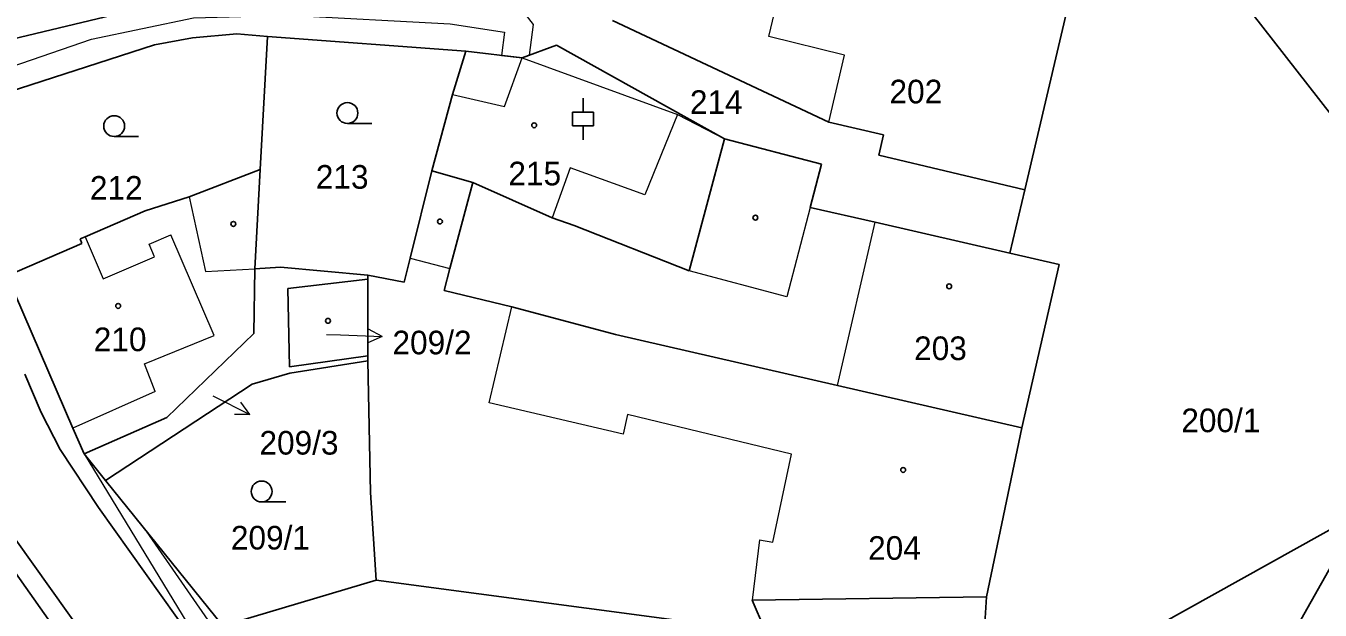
# Model space of a CAD drawing. Extents: x -727701 to -724405, y -960481 to -957284.
# Drawn here: x -726900.7 to -726807.6, y -958127.7 to -958085.7 of the extents above; entities that cross this region are included whole.
import ezdxf
from ezdxf.enums import TextEntityAlignment as Align

# ---------------------------------------------------------------- set-up
doc = ezdxf.new("R2010")
doc.units = 0
doc.header["$LTSCALE"] = 0.68
for name, color, linetype, lineweight in [('1', 7, 'Continuous', 25), ('13', 7, 'Continuous', 13), ('3', 7, 'Continuous', 25), ('4', 7, 'Continuous', 13), ('5', 7, 'Continuous', 25), ('7', 7, 'Continuous', 13)]:
    doc.layers.add(name, color=color, linetype=linetype, lineweight=lineweight)
doc.layers.add('2', color=7, linetype='Continuous')

msp = doc.modelspace()

# ---------------------------------------------------------------- linework, layer by layer
at = {"layer": '1'}
for p, q in [((-726828.85, -958097.47), (-726824.94, -958080.83)), ((-726906.79, -958087.87), (-726889.47, -958083.69)), ((-726813.46, -958083.54), (-726806.79, -958092.11)), ((-726858.5, -958085.29), (-726842.95, -958092.6)), ((-726891.47, -958087.04), (-726888.72, -958086.55)), ((-726888.72, -958086.55), (-726885.54, -958086.26)), ((-726885.54, -958086.26), (-726883.34, -958086.44)), ((-726883.34, -958086.44), (-726883.86, -958096.02)), ((-726883.34, -958086.44), (-726869.05, -958087.51)), ((-726905.66, -958091.62), (-726891.47, -958087.04)), ((-726869.05, -958087.51), (-726870.03, -958090.61)), ((-726869.05, -958087.51), (-726865.02, -958087.99)), ((-726865.02, -958087.99), (-726862.53, -958087.06)), ((-726862.53, -958087.06), (-726850.45, -958093.8)), ((-726870.03, -958090.61), (-726871.51, -958096.12)), ((-726842.95, -958092.6), (-726839, -958093.53)), ((-726852.99, -958103.3), (-726850.45, -958093.8)), ((-726850.45, -958093.8), (-726843.47, -958095.64)), ((-726839, -958093.53), (-726839.35, -958094.99)), ((-726839.35, -958094.99), (-726828.85, -958097.47)), ((-726888.97, -958097.99), (-726883.86, -958096.02)), ((-726883.86, -958096.02), (-726884.25, -958103.15)), ((-726871.51, -958096.12), (-726873.07, -958102.39)), ((-726871.51, -958096.12), (-726868.57, -958096.96)), ((-726843.47, -958095.64), (-726844.28, -958098.74)), ((-726868.57, -958096.96), (-726870.21, -958103.14)), ((-726868.57, -958096.96), (-726862.84, -958099.48)), ((-726892.13, -958098.99), (-726888.97, -958097.99)), ((-726829.92, -958102.03), (-726828.85, -958097.47)), ((-726844.28, -958098.74), (-726839.62, -958099.81)), ((-726896.46, -958100.86), (-726892.13, -958098.99)), ((-726862.84, -958099.48), (-726861.27, -958100.05)), ((-726839.62, -958099.81), (-726829.92, -958102.03)), ((-726861.27, -958100.05), (-726852.99, -958103.3)), ((-726902.07, -958103.67), (-726896.68, -958101.34)), ((-726896.82, -958101.01), (-726896.46, -958100.86)), ((-726896.68, -958101.34), (-726896.82, -958101.01)), ((-726873.07, -958102.39), (-726873.5, -958104.12)), ((-726826.37, -958102.84), (-726829.92, -958102.03)), ((-726884.25, -958103.15), (-726884.31, -958107.82)), ((-726884.25, -958103.15), (-726882.4, -958103.04)), ((-726882.4, -958103.04), (-726876.12, -958103.62)), ((-726870.21, -958103.14), (-726870.62, -958104.72)), ((-726829.05, -958114.59), (-726826.37, -958102.84)), ((-726902.07, -958103.67), (-726897.34, -958114.63)), ((-726881.88, -958104.58), (-726876.12, -958103.9)), ((-726876.12, -958103.62), (-726876.12, -958103.9)), ((-726876.12, -958103.62), (-726873.5, -958104.12)), ((-726876.12, -958103.9), (-726876.12, -958109.43)), ((-726881.74, -958110.21), (-726881.88, -958104.58)), ((-726870.62, -958104.72), (-726865.76, -958105.89)), ((-726865.76, -958105.89), (-726858.3, -958107.89)), ((-726890.58, -958113.85), (-726884.31, -958107.82)), ((-726858.3, -958107.89), (-726842.31, -958111.55)), ((-726876.12, -958109.43), (-726881.74, -958110.21)), ((-726876.12, -958109.77), (-726881.73, -958110.66)), ((-726876.12, -958109.43), (-726876.12, -958109.77)), ((-726875.92, -958119.26), (-726876.12, -958109.77)), ((-726899.61, -958113.49), (-726900.79, -958110.74)), ((-726881.73, -958110.66), (-726884.43, -958111.46)), ((-726884.43, -958111.46), (-726894.98, -958118.38)), ((-726842.31, -958111.55), (-726829.05, -958114.59)), ((-726881.62, -958150.46), (-726907.75, -958113.81)), ((-726898.24, -958116.16), (-726899.61, -958113.49)), ((-726908.91, -958114.63), (-726880.41, -958154.56)), ((-726897.34, -958114.63), (-726896.52, -958116.48)), ((-726896.52, -958116.48), (-726890.58, -958113.85)), ((-726829.05, -958114.59), (-726831.59, -958126.77)), ((-726895.48, -958120.34), (-726898.24, -958116.16)), ((-726896.52, -958116.48), (-726894.98, -958118.38)), ((-726894.98, -958118.38), (-726886.54, -958128.84)), ((-726875.52, -958125.55), (-726875.92, -958119.26)), ((-726886.44, -958133.03), (-726895.48, -958120.34)), ((-726831.7, -958135.75), (-726804.64, -958120.66)), ((-726808.98, -958128.42), (-726804.64, -958120.66)), ((-726886.54, -958128.84), (-726875.52, -958125.55)), ((-726875.52, -958125.55), (-726852.99, -958128.56)), ((-726848.46, -958127.01), (-726831.59, -958126.77)), ((-726831.59, -958126.77), (-726832.13, -958135.17)), ((-726848.46, -958127.01), (-726847.57, -958129.07))]:
    msp.add_line(p, q, dxfattribs=at)
at = {"layer": '13'}
for points in [[(-726881.32, -958083.06), (-726889.47, -958083.69), (-726906.79, -958087.87), (-726906.11, -958090.11), (-726895.99, -958086.64), (-726888.66, -958085.1), (-726881.81, -958084.9), (-726870.2, -958085.53), (-726866.28, -958086.13), (-726866.49, -958087.81), (-726865.02, -958087.99), (-726864.47, -958087.79), (-726864.2, -958085.58), (-726864.93, -958084.62), (-726865.48, -958084.56), (-726869.32, -958083.69), (-726877.28, -958083.06), (-726878.58, -958082.9)], [(-726896.52, -958116.48), (-726886.44, -958133.03), (-726883.28, -958137.41), (-726882.01, -958136.37), (-726884.42, -958133.04), (-726892.03, -958122.04)]]:
    msp.add_lwpolyline(points, close=True, dxfattribs=at)
at = {"layer": '3'}
for p, q in [((-726860.63, -958091.881), (-726860.63, -958090.88)), ((-726861.381, -958091.881), (-726859.879, -958091.881)), ((-726861.381, -958092.882), (-726861.381, -958091.881)), ((-726859.879, -958092.882), (-726859.879, -958091.881)), ((-726877.583, -958092.7), (-726875.833, -958092.7)), ((-726861.381, -958092.882), (-726859.879, -958092.882)), ((-726860.63, -958093.88), (-726860.63, -958092.882)), ((-726894.363, -958093.64), (-726892.613, -958093.64)), ((-726883.753, -958119.93), (-726882.003, -958119.93))]:
    msp.add_line(p, q, dxfattribs=at)
for centre in [(-726877.5829, -958091.9498), (-726894.3629, -958092.8898), (-726883.7529, -958119.1798)]:
    msp.add_circle(centre, 0.75, dxfattribs=at)
at = {"layer": '4'}
for p, q in [((-726847.27, -958086.45), (-726845.48, -958079.04)), ((-726841.81, -958087.78), (-726847.27, -958086.45)), ((-726866.27, -958091.48), (-726865.02, -958087.99)), ((-726865.02, -958087.99), (-726853.84, -958092.05)), ((-726842.95, -958092.6), (-726841.81, -958087.78)), ((-726870.03, -958090.61), (-726866.27, -958091.48)), ((-726853.84, -958092.05), (-726856.18, -958097.84)), ((-726853.84, -958092.05), (-726850.45, -958093.8)), ((-726861.55, -958095.9), (-726862.84, -958099.48)), ((-726856.18, -958097.84), (-726861.55, -958095.9)), ((-726888.97, -958097.99), (-726887.79, -958103.35)), ((-726844.28, -958098.74), (-726845.97, -958105.18)), ((-726842.31, -958111.55), (-726839.62, -958099.81)), ((-726891.85, -958101.38), (-726890.29, -958100.72)), ((-726887.18, -958107.96), (-726890.29, -958100.72)), ((-726896.46, -958100.86), (-726895.16, -958103.89)), ((-726891.46, -958102.3), (-726891.85, -958101.38)), ((-726895.16, -958103.89), (-726891.46, -958102.3)), ((-726873.07, -958102.39), (-726870.21, -958103.14)), ((-726887.79, -958103.35), (-726884.25, -958103.15)), ((-726845.97, -958105.18), (-726852.99, -958103.3)), ((-726867.39, -958112.8), (-726865.76, -958105.89)), ((-726892.19, -958110), (-726887.18, -958107.96)), ((-726891.41, -958111.99), (-726892.19, -958110)), ((-726891.41, -958111.99), (-726897.34, -958114.63)), ((-726857.75, -958115.06), (-726867.39, -958112.8)), ((-726857.42, -958113.65), (-726857.75, -958115.06)), ((-726845.62, -958116.5), (-726857.42, -958113.65)), ((-726846.98, -958122.82), (-726845.62, -958116.5)), ((-726847.94, -958122.65), (-726848.46, -958127.01)), ((-726847.94, -958122.65), (-726846.98, -958122.82))]:
    msp.add_line(p, q, dxfattribs=at)
at = {"layer": '5'}
for centre in [(-726864.1468, -958092.8292), (-726885.7868, -958099.9292), (-726870.9268, -958099.7592), (-726848.2268, -958099.4792), (-726834.2868, -958104.4192), (-726894.0768, -958105.8292), (-726878.9768, -958106.8992), (-726837.5968, -958117.6292)]:
    msp.add_circle(centre, 0.175, dxfattribs=at)
at = {"layer": '7'}
for p, q in [((-726875.091, -958108.025), (-726876.074, -958107.489)), ((-726884.596, -958113.652), (-726885.261, -958112.752))]:
    msp.add_line(p, q, dxfattribs=at)
for points in [[(-726879.08, -958107.89), (-726878.09, -958107.92), (-726875.091, -958108.025), (-726876.109, -958108.49)], [(-726887.27, -958112.29), (-726884.596, -958113.652), (-726885.716, -958113.644)]]:
    msp.add_lwpolyline(points, dxfattribs=at)

# ---------------------------------------------------------------- texts
at = {"layer": '2'}
for s, p in [('202', (-726838.58, -958091.255)), ('214', (-726852.94, -958092.015)), ('215', (-726866, -958097.155)), ('212', (-726896.11, -958098.185)), ('210', (-726895.83, -958109.085)), ('209/2', (-726874.34, -958109.312)), ('203', (-726836.81, -958109.725)), ('209/3', (-726883.91, -958116.525)), ('204', (-726840.12, -958124.095))]:
    msp.add_text(s, height=1.7, dxfattribs=at).set_placement(p)
for s, p in [('213', (-726877.959, -958097.395)), ('200/1', (-726814.74, -958114.915)), ('209/1', (-726883.12, -958123.355))]:
    msp.add_text(s, height=1.7, dxfattribs=at).set_placement(p, align=Align.CENTER)

doc.saveas('drawing.dxf')
